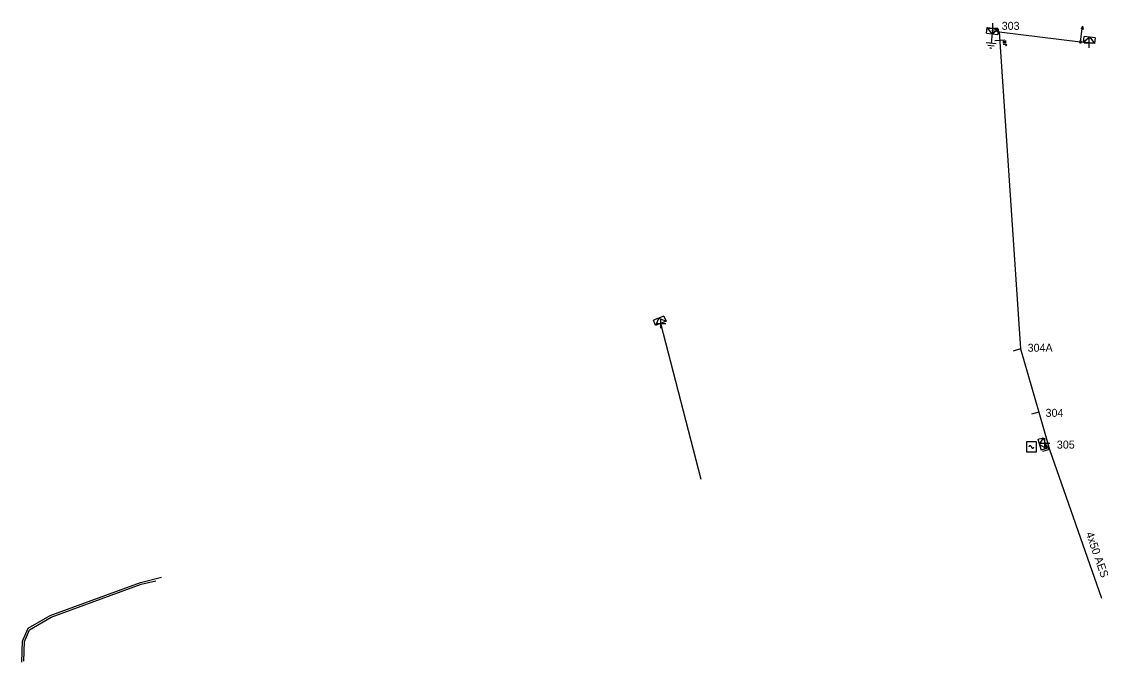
# Model space of a CAD drawing. Extents: x -540247 to -537390, y -1183887 to -1180355.
# Drawn here: x -538261.2 to -538125.4, y -1180644.4 to -1180564.3 of the extents above; entities that cross this region are included whole.
import ezdxf

# ---------------------------------------------------------------- set-up
doc = ezdxf.new("R2010")
doc.units = 0
for name, color, linetype in [('Vrstva 1', 7, 'Continuous'), ('Vrstva 13', 7, 'Continuous'), ('Vrstva 14', 7, 'Continuous'), ('Vrstva 15', 7, 'Continuous'), ('Vrstva 18', 7, 'Continuous'), ('Vrstva 2', 7, 'Continuous'), ('Vrstva 31', 7, 'Continuous'), ('Vrstva 34', 7, 'Continuous'), ('Vrstva 5', 7, 'Continuous'), ('Vrstva 50', 7, 'Continuous'), ('Vrstva 51', 7, 'Continuous'), ('Vrstva 52', 7, 'Continuous'), ('Vrstva 54', 7, 'Continuous'), ('Vrstva 8', 7, 'Continuous'), ('Vrstva 9', 7, 'Continuous')]:
    doc.layers.add(name, color=color, linetype=linetype)

# ---------------------------------------------------------------- blocks, each defined once
blk = doc.blocks.new('NN560')
at = {"layer": 'Vrstva 2'}
for points in [[(2, 0), (1.59, 0.14)], [(0, 0), (2, 0)], [(2, 0), (1.59, -0.13)]]:
    blk.add_lwpolyline(points, dxfattribs=at)
blk = doc.blocks.new('NN840')
at = {"layer": 'Vrstva 15'}
for points in [[(0, 0.62), (0, -0.63)], [(-0.75, -0.71), (-0.75, -0.66)], [(-0.73, -0.76), (-0.75, -0.71)], [(-0.66, -0.8), (-0.73, -0.76)], [(-0.63, -0.8), (-0.66, -0.8)], [(-0.56, -0.76), (-0.63, -0.8)], [(-0.54, -0.71), (-0.56, -0.76)], [(-0.54, -0.38), (-0.54, -0.71)], [(-0.33, -0.38), (-0.33, -0.8)], [(-0.33, -0.64), (-0.13, -0.38)], [(-0.26, -0.56), (-0.09, -0.8)]]:
    blk.add_lwpolyline(points, dxfattribs=at)
blk = doc.blocks.new('NN800')
at = {"layer": 'Vrstva 1'}
for points in [[(-0.44, 0.44), (0.44, -0.44)], [(-0.44, -0.44), (0.44, 0.44)]]:
    blk.add_lwpolyline(points, dxfattribs=at)
blk = doc.blocks.new('NN630')
at = {"layer": 'Vrstva 9'}
for points in [[(0, -0.7), (-0.7, 0)], [(-0.7, -0.7), (-0.7, 0), (0.7, 0), (0.7, -0.7)], [(-0.7, -0.7), (0.7, -0.7)], [(0, -0.7), (0.7, 0)]]:
    blk.add_lwpolyline(points, dxfattribs=at)
blk = doc.blocks.new('NN810')
at = {"layer": 'Vrstva 14'}
for points in [[(0, -0.64), (0, -1.89)], [(0.63, -1.89), (-0.62, -1.89)], [(0.39, -2.2), (-0.4, -2.2)], [(0, -2.52), (-0.12, -2.52)], [(0.14, -2.52), (0, -2.52)]]:
    blk.add_lwpolyline(points, dxfattribs=at)
blk = doc.blocks.new('NN740')
at = {"layer": 'Vrstva 1'}
for points in [[(0.62, 0.62), (-0.63, 0.62)], [(-0.63, 0.62), (-0.63, -0.63)], [(0, 0), (0, 0.01), (0, 0.03), (-0.01, 0.05), (-0.01, 0.06), (-0.02, 0.08), (-0.03, 0.09), (-0.04, 0.1), (-0.05, 0.11), (-0.06, 0.12), (-0.08, 0.13), (-0.09, 0.14), (-0.11, 0.14), (-0.12, 0.15), (-0.14, 0.15), (-0.15, 0.15), (-0.17, 0.15), (-0.18, 0.15), (-0.2, 0.15), (-0.21, 0.14), (-0.23, 0.13), (-0.24, 0.12), (-0.26, 0.11), (-0.27, 0.1), (-0.28, 0.09), (-0.29, 0.08), (-0.29, 0.06), (-0.3, 0.05), (-0.3, 0.03), (-0.31, 0.02), (-0.31, 0), (-0.31, 0)], [(0.62, -0.63), (0.62, 0.62)], [(-0.63, -0.63), (0.62, -0.63)], [(0, 0), (0, -0.02), (0, -0.03), (0.01, -0.05), (0.01, -0.06), (0.02, -0.08), (0.03, -0.09), (0.04, -0.1), (0.05, -0.11), (0.06, -0.12), (0.07, -0.13), (0.09, -0.14), (0.1, -0.15), (0.12, -0.15), (0.13, -0.15), (0.15, -0.15), (0.16, -0.15), (0.18, -0.15), (0.19, -0.15), (0.21, -0.14), (0.22, -0.14), (0.24, -0.13), (0.25, -0.12), (0.26, -0.11), (0.27, -0.09), (0.28, -0.08), (0.29, -0.07), (0.29, -0.05), (0.3, -0.04), (0.3, -0.02), (0.3, -0.01), (0.3, -0.01)]]:
    blk.add_lwpolyline(points, dxfattribs=at)
blk = doc.blocks.new('NN500')
at = {"layer": 'Vrstva 2'}
for points in [[(0, -0.24), (0.02, -0.23), (0.05, -0.23), (0.07, -0.22), (0.09, -0.22), (0.12, -0.2), (0.14, -0.19), (0.16, -0.18), (0.17, -0.16), (0.19, -0.14), (0.2, -0.12), (0.21, -0.1), (0.22, -0.07), (0.23, -0.05), (0.23, -0.02), (0.23, 0), (0.23, 0.02), (0.23, 0.05), (0.22, 0.07), (0.21, 0.1), (0.2, 0.12), (0.19, 0.14), (0.17, 0.16), (0.16, 0.17), (0.14, 0.19), (0.12, 0.2), (0.09, 0.21), (0.07, 0.22), (0.05, 0.23), (0.02, 0.23), (0, 0.23), (-0.03, 0.23), (-0.05, 0.23), (-0.07, 0.22), (-0.1, 0.21), (-0.12, 0.2), (-0.14, 0.19), (-0.16, 0.17), (-0.18, 0.16), (-0.19, 0.14), (-0.2, 0.12), (-0.22, 0.1), (-0.22, 0.07), (-0.23, 0.05), (-0.23, 0.02), (-0.24, 0), (-0.23, -0.02), (-0.23, -0.05), (-0.22, -0.07), (-0.22, -0.1), (-0.2, -0.12), (-0.19, -0.14), (-0.18, -0.16), (-0.16, -0.18), (-0.14, -0.19), (-0.12, -0.2), (-0.1, -0.22), (-0.07, -0.22), (-0.05, -0.23), (-0.03, -0.23), (0, -0.24)], [(0, -0.24), (0.02, -0.23), (0.05, -0.23), (0.07, -0.22), (0.09, -0.22), (0.12, -0.2), (0.14, -0.19), (0.16, -0.18), (0.17, -0.16), (0.19, -0.14), (0.2, -0.12), (0.21, -0.1), (0.22, -0.07), (0.23, -0.05), (0.23, -0.02), (0.23, 0), (0.23, 0.02), (0.23, 0.05), (0.22, 0.07), (0.21, 0.1), (0.2, 0.12), (0.19, 0.14), (0.17, 0.16), (0.16, 0.17), (0.14, 0.19), (0.12, 0.2), (0.09, 0.21), (0.07, 0.22), (0.05, 0.23), (0.02, 0.23), (0, 0.23), (-0.03, 0.23), (-0.05, 0.23), (-0.07, 0.22), (-0.1, 0.21), (-0.12, 0.2), (-0.14, 0.19), (-0.16, 0.17), (-0.18, 0.16), (-0.19, 0.14), (-0.2, 0.12), (-0.22, 0.1), (-0.22, 0.07), (-0.23, 0.05), (-0.23, 0.02), (-0.24, 0), (-0.23, -0.02), (-0.23, -0.05), (-0.22, -0.07), (-0.22, -0.1), (-0.2, -0.12), (-0.19, -0.14), (-0.18, -0.16), (-0.16, -0.18), (-0.14, -0.19), (-0.12, -0.2), (-0.1, -0.22), (-0.07, -0.22), (-0.05, -0.23), (-0.03, -0.23), (0, -0.24)], [(0, -0.21), (0.02, -0.2), (0.04, -0.2), (0.06, -0.2), (0.08, -0.19), (0.1, -0.18), (0.12, -0.17), (0.14, -0.15), (0.15, -0.14), (0.16, -0.12), (0.18, -0.1), (0.19, -0.08), (0.19, -0.06), (0.2, -0.04), (0.2, -0.02), (0.2, 0), (0.2, 0.02), (0.2, 0.04), (0.19, 0.06), (0.19, 0.08), (0.18, 0.1), (0.16, 0.12), (0.15, 0.14), (0.14, 0.15), (0.12, 0.17), (0.1, 0.18), (0.08, 0.19), (0.06, 0.19), (0.04, 0.2), (0.02, 0.2), (0, 0.2), (-0.02, 0.2), (-0.04, 0.2), (-0.06, 0.19), (-0.08, 0.19), (-0.1, 0.18), (-0.12, 0.17), (-0.14, 0.15), (-0.15, 0.14), (-0.17, 0.12), (-0.18, 0.1), (-0.19, 0.08), (-0.2, 0.06), (-0.2, 0.04), (-0.21, 0.02), (-0.21, 0), (-0.21, -0.02), (-0.2, -0.04), (-0.2, -0.06), (-0.19, -0.08), (-0.18, -0.1), (-0.17, -0.12), (-0.15, -0.14), (-0.14, -0.15), (-0.12, -0.17), (-0.1, -0.18), (-0.08, -0.19), (-0.06, -0.2), (-0.04, -0.2), (-0.02, -0.2), (0, -0.21)], [(0, -0.18), (0.02, -0.18), (0.04, -0.17), (0.05, -0.17), (0.07, -0.16), (0.09, -0.15), (0.1, -0.14), (0.12, -0.13), (0.13, -0.12), (0.14, -0.1), (0.15, -0.09), (0.16, -0.07), (0.17, -0.05), (0.17, -0.04), (0.17, -0.02), (0.17, 0), (0.17, 0.02), (0.17, 0.04), (0.17, 0.05), (0.16, 0.07), (0.15, 0.09), (0.14, 0.1), (0.13, 0.12), (0.12, 0.13), (0.1, 0.14), (0.09, 0.15), (0.07, 0.16), (0.05, 0.17), (0.04, 0.17), (0.02, 0.17), (0, 0.18), (-0.02, 0.17), (-0.04, 0.17), (-0.06, 0.17), (-0.07, 0.16), (-0.09, 0.15), (-0.1, 0.14), (-0.12, 0.13), (-0.13, 0.12), (-0.14, 0.1), (-0.15, 0.09), (-0.16, 0.07), (-0.17, 0.05), (-0.17, 0.04), (-0.18, 0.02), (-0.18, 0), (-0.18, -0.02), (-0.17, -0.04), (-0.17, -0.05), (-0.16, -0.07), (-0.15, -0.09), (-0.14, -0.1), (-0.13, -0.12), (-0.12, -0.13), (-0.1, -0.14), (-0.09, -0.15), (-0.07, -0.16), (-0.06, -0.17), (-0.04, -0.17), (-0.02, -0.18), (0, -0.18)], [(0, -0.15), (0.01, -0.15), (0.03, -0.14), (0.04, -0.14), (0.06, -0.13), (0.07, -0.13), (0.08, -0.12), (0.1, -0.11), (0.11, -0.1), (0.12, -0.09), (0.13, -0.07), (0.13, -0.06), (0.14, -0.05), (0.14, -0.03), (0.14, -0.02), (0.14, 0), (0.14, 0.01), (0.14, 0.03), (0.14, 0.04), (0.13, 0.06), (0.13, 0.07), (0.12, 0.09), (0.11, 0.1), (0.1, 0.11), (0.08, 0.12), (0.07, 0.13), (0.06, 0.13), (0.04, 0.14), (0.03, 0.14), (0.01, 0.14), (0, 0.15), (-0.02, 0.14), (-0.03, 0.14), (-0.05, 0.14), (-0.06, 0.13), (-0.07, 0.13), (-0.09, 0.12), (-0.1, 0.11), (-0.11, 0.1), (-0.12, 0.09), (-0.13, 0.07), (-0.13, 0.06), (-0.14, 0.04), (-0.14, 0.03), (-0.15, 0.01), (-0.15, 0), (-0.15, -0.02), (-0.14, -0.03), (-0.14, -0.05), (-0.13, -0.06), (-0.13, -0.07), (-0.12, -0.09), (-0.11, -0.1), (-0.1, -0.11), (-0.09, -0.12), (-0.07, -0.13), (-0.06, -0.13), (-0.05, -0.14), (-0.03, -0.14), (-0.02, -0.15), (0, -0.15)], [(0, -0.12), (0.01, -0.12), (0.02, -0.11), (0.03, -0.11), (0.05, -0.11), (0.06, -0.1), (0.07, -0.09), (0.08, -0.09), (0.09, -0.08), (0.09, -0.07), (0.1, -0.06), (0.11, -0.05), (0.11, -0.04), (0.11, -0.02), (0.11, -0.01), (0.12, 0), (0.11, 0.01), (0.11, 0.02), (0.11, 0.04), (0.11, 0.05), (0.1, 0.06), (0.09, 0.07), (0.09, 0.08), (0.08, 0.09), (0.07, 0.09), (0.06, 0.1), (0.05, 0.11), (0.03, 0.11), (0.02, 0.11), (0.01, 0.12), (0, 0.12), (-0.01, 0.12), (-0.03, 0.11), (-0.04, 0.11), (-0.05, 0.11), (-0.06, 0.1), (-0.07, 0.09), (-0.08, 0.09), (-0.09, 0.08), (-0.1, 0.07), (-0.1, 0.06), (-0.11, 0.05), (-0.11, 0.04), (-0.12, 0.02), (-0.12, 0.01), (-0.12, 0), (-0.12, -0.01), (-0.12, -0.02), (-0.11, -0.04), (-0.11, -0.05), (-0.1, -0.06), (-0.1, -0.07), (-0.09, -0.08), (-0.08, -0.09), (-0.07, -0.09), (-0.06, -0.1), (-0.05, -0.11), (-0.04, -0.11), (-0.03, -0.11), (-0.01, -0.12), (0, -0.12)], [(0, -0.09), (0.01, -0.09), (0.02, -0.09), (0.03, -0.08), (0.03, -0.08), (0.04, -0.08), (0.05, -0.07), (0.06, -0.07), (0.06, -0.06), (0.07, -0.05), (0.07, -0.04), (0.08, -0.04), (0.08, -0.03), (0.08, -0.02), (0.09, -0.01), (0.09, 0), (0.09, 0.01), (0.08, 0.02), (0.08, 0.03), (0.08, 0.03), (0.07, 0.04), (0.07, 0.05), (0.06, 0.06), (0.06, 0.06), (0.05, 0.07), (0.04, 0.07), (0.03, 0.08), (0.03, 0.08), (0.02, 0.08), (0.01, 0.09), (0, 0.09), (-0.01, 0.09), (-0.02, 0.08), (-0.03, 0.08), (-0.04, 0.08), (-0.04, 0.07), (-0.05, 0.07), (-0.06, 0.06), (-0.07, 0.06), (-0.07, 0.05), (-0.08, 0.04), (-0.08, 0.03), (-0.08, 0.03), (-0.09, 0.02), (-0.09, 0.01), (-0.09, 0), (-0.09, -0.01), (-0.09, -0.02), (-0.08, -0.03), (-0.08, -0.04), (-0.08, -0.04), (-0.07, -0.05), (-0.07, -0.06), (-0.06, -0.07), (-0.05, -0.07), (-0.04, -0.08), (-0.04, -0.08), (-0.03, -0.08), (-0.02, -0.09), (-0.01, -0.09), (0, -0.09)], [(0, -0.06), (0, -0.06), (0.01, -0.06), (0.02, -0.05), (0.02, -0.05), (0.03, -0.05), (0.03, -0.05), (0.04, -0.04), (0.04, -0.04), (0.05, -0.03), (0.05, -0.03), (0.05, -0.02), (0.05, -0.02), (0.05, -0.01), (0.06, -0.01), (0.06, 0), (0.06, 0.01), (0.05, 0.01), (0.05, 0.02), (0.05, 0.02), (0.05, 0.03), (0.05, 0.03), (0.04, 0.04), (0.04, 0.04), (0.03, 0.05), (0.03, 0.05), (0.02, 0.05), (0.02, 0.05), (0.01, 0.06), (0, 0.06), (0, 0.06), (-0.01, 0.06), (-0.01, 0.06), (-0.02, 0.05), (-0.02, 0.05), (-0.03, 0.05), (-0.03, 0.05), (-0.04, 0.04), (-0.04, 0.04), (-0.05, 0.03), (-0.05, 0.03), (-0.05, 0.02), (-0.06, 0.02), (-0.06, 0.01), (-0.06, 0.01), (-0.06, 0), (-0.06, -0.01), (-0.06, -0.01), (-0.06, -0.02), (-0.05, -0.02), (-0.05, -0.03), (-0.05, -0.03), (-0.04, -0.04), (-0.04, -0.04), (-0.03, -0.05), (-0.03, -0.05), (-0.02, -0.05), (-0.02, -0.05), (-0.01, -0.06), (-0.01, -0.06), (0, -0.06)], [(0, -0.03), (0, -0.03), (0, -0.03), (0.01, -0.03), (0.01, -0.03), (0.01, -0.02), (0.02, -0.02), (0.02, -0.02), (0.02, -0.02), (0.02, -0.02), (0.02, -0.01), (0.02, -0.01), (0.03, -0.01), (0.03, -0.01), (0.03, 0), (0.03, 0), (0.03, 0), (0.03, 0.01), (0.03, 0.01), (0.02, 0.01), (0.02, 0.01), (0.02, 0.02), (0.02, 0.02), (0.02, 0.02), (0.02, 0.02), (0.01, 0.02), (0.01, 0.02), (0.01, 0.03), (0, 0.03), (0, 0.03), (0, 0.03), (0, 0.03), (-0.01, 0.03), (-0.01, 0.03), (-0.01, 0.02), (-0.02, 0.02), (-0.02, 0.02), (-0.02, 0.02), (-0.02, 0.02), (-0.02, 0.02), (-0.03, 0.01), (-0.03, 0.01), (-0.03, 0.01), (-0.03, 0.01), (-0.03, 0), (-0.03, 0), (-0.03, 0), (-0.03, -0.01), (-0.03, -0.01), (-0.03, -0.01), (-0.03, -0.01), (-0.02, -0.02), (-0.02, -0.02), (-0.02, -0.02), (-0.02, -0.02), (-0.02, -0.02), (-0.01, -0.03), (-0.01, -0.03), (-0.01, -0.03), (0, -0.03), (0, -0.03)], [(0.23, 0), (0.7, 0)]]:
    blk.add_lwpolyline(points, dxfattribs=at)
blk = doc.blocks.new('NN510')
at = {"layer": 'Vrstva 2'}
blk.add_lwpolyline([(0, 0), (0, 0.94)], dxfattribs=at)

msp = doc.modelspace()

# ---------------------------------------------------------------- linework, layer by layer
at = {"layer": 'Vrstva 5'}
for points in [[(-538261.18, -1180644.43), (-538261.06, -1180641.77), (-538260.39, -1180640.17), (-538257.62, -1180638.58), (-538246.32, -1180634.44), (-538243.7, -1180633.8)], [(-538260.92, -1180644.27), (-538260.82, -1180641.83), (-538260.19, -1180640.35), (-538257.52, -1180638.8), (-538246.24, -1180634.68), (-538244.41, -1180634.23)]]:
    msp.add_lwpolyline(points, dxfattribs=at)
at = {"layer": 'Vrstva 50'}
msp.add_lwpolyline([(-538139.08, -1180565.62), (-538136.42, -1180605.25), (-538134.13, -1180613.16), (-538132.77, -1180617.82), (-538126.28, -1180636.41)], dxfattribs=at)
at = {"layer": 'Vrstva 52'}
msp.add_lwpolyline([(-538176.32, -1180621.56), (-538181.34, -1180602.05)], dxfattribs=at)
at = {"layer": 'Vrstva 54'}
msp.add_lwpolyline([(-538139.08, -1180565.62), (-538128.92, -1180566.86), (-538127.85, -1180566.98)], dxfattribs=at)
at = {"layer": 'Vrstva 8'}
for points in [[(-538139.08, -1180565.62), (-538139.88, -1180565.15)], [(-538132.77, -1180617.82), (-538133.36, -1180617.02)]]:
    msp.add_lwpolyline(points, dxfattribs=at)

# ---------------------------------------------------------------- block references
at = {"layer": 'Vrstva 13'}
for name, p, rotation in [('NN560', (-538128.92, -1180566.86), 82.2323444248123), ('NN510', (-538139.08, -1180565.62), 82.11431108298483), ('NN510', (-538136.42, -1180605.25), 106.00159991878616), ('NN510', (-538134.13, -1180613.16), 105.10636664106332), ('NN510', (-538132.77, -1180617.82), 105.10636667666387)]:
    msp.add_blockref(name, p, dxfattribs=dict(at, rotation=rotation))
at = {"layer": 'Vrstva 13', "xscale": 0.5, "yscale": 0.49999999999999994, "rotation": 82.17199998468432}
msp.add_blockref('NN500', (-538128.92, -1180566.86), dxfattribs=at)
at = {"layer": 'Vrstva 15', "rotation": -5.8069473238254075}
msp.add_blockref('NN810', (-538139.88, -1180565.15), dxfattribs=at)
at = {"layer": 'Vrstva 18', "rotation": 93.83844720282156}
msp.add_blockref('NN840', (-538139.01, -1180566.65), dxfattribs=at)
at = {"layer": 'Vrstva 31'}
for p, rotation in [((-538139.88, -1180565.15), -5.8069473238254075), ((-538127.85, -1180566.98), 172.93654433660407), ((-538181.34, -1180602.05), -158.3128304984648), ((-538133.36, -1180617.02), -73.99840004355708)]:
    msp.add_blockref('NN630', p, dxfattribs=dict(at, rotation=rotation))
at = {"layer": 'Vrstva 34'}
for p, rotation in [((-538139.88, -1180565.15), 44.99999995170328), ((-538127.85, -1180566.98), 45), ((-538181.34, -1180602.05), 45.00000009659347), ((-538133.36, -1180617.02), 45)]:
    msp.add_blockref('NN800', p, dxfattribs=dict(at, rotation=rotation))
msp.add_blockref('NN740', (-538135.05, -1180617.5), dxfattribs=at)

# ---------------------------------------------------------------- texts
at = {"layer": 'Vrstva 14'}
for s, p in [('303', (-538138.76, -1180565.35)), ('304A', (-538135.52, -1180605.6)), ('304', (-538133.28, -1180613.74)), ('305', (-538131.87, -1180617.71))]:
    msp.add_text(s, height=1, dxfattribs=at).set_placement(p)
at = {"layer": 'Vrstva 51'}
msp.add_text('4x50 AES', height=1, rotation=289.237, dxfattribs=at).set_placement((-538128.27, -1180628.32))

doc.saveas('drawing.dxf')
